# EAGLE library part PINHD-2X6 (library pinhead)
PIN HEADER
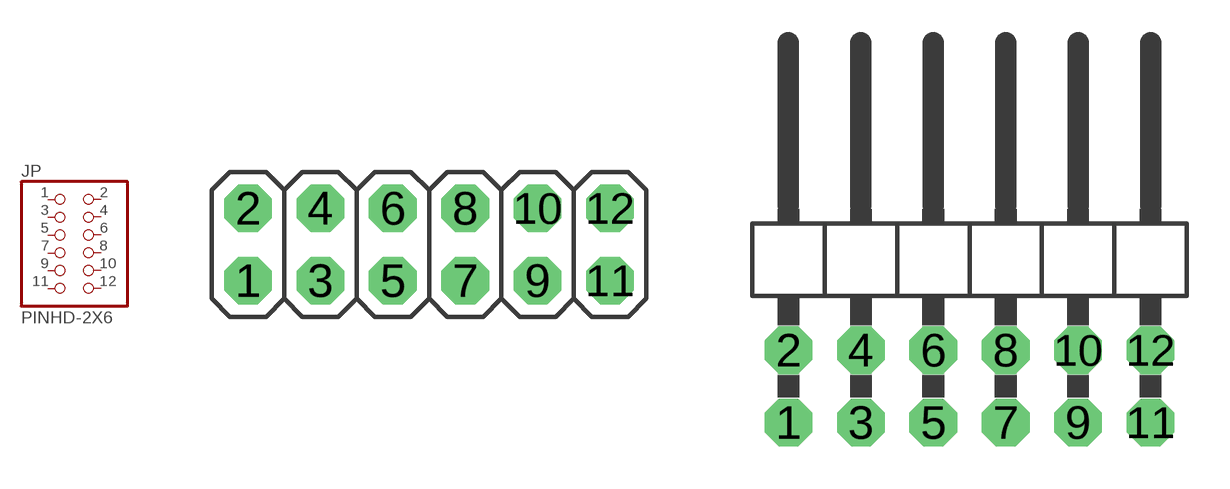
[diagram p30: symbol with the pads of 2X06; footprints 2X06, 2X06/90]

Designator prefix JP

## PINHD-2X6  [2X06]
1  1  pas
2  2  pas
3  3  pas
4  4  pas
5  5  pas
6  6  pas
7  7  pas
8  8  pas
9  9  pas
10  10  pas
11  11  pas
12  12  pas

## PINHD-2X6/90  [2X06/90]
Pads as for 2X06

## Footprint 2X06 (pad centres in mm)
PIN HEADER
drill 1.016 pad 1.67 octagon: 1 -6.35,-1.27; 2 -6.35,1.27; 3 -3.81,-1.27; 4 -3.81,1.27; 5 -1.27,-1.27; 6 -1.27,1.27; 7 1.27,-1.27; 8 1.27,1.27; 9 3.81,-1.27; 10 3.81,1.27; 11 6.35,-1.27; 12 6.35,1.27

## Footprint 2X06/90 (pad centres in mm)
PIN HEADER
drill 1.016 pad 1.67 octagon: 1 -6.35,-6.35; 2 -6.35,-3.81; 3 -3.81,-6.35; 4 -3.81,-3.81; 5 -1.27,-6.35; 6 -1.27,-3.81; 7 1.27,-6.35; 8 1.27,-3.81; 9 3.81,-6.35; 10 3.81,-3.81; 11 6.35,-6.35; 12 6.35,-3.81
